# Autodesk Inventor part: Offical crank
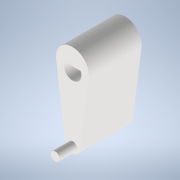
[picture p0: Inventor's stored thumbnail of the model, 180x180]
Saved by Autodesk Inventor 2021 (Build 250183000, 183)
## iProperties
Created: 2021-01
Part Number: Offical crank
Material: Generic
Document SubType Name: Modeling
Designer: Owner
Density: 1 g/cm^3
Appearance: Default
Author: Owner
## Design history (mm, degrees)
sketch "Sketch1"
  geometry: L1 (-4.752, 14.66)-(-2.155, -4.465); L2 (4.537, 14.628)-(2.038, -4.487); A1 r 4.682 centre (-0.106, 15.234) between (4.537, 14.628) and (-4.752, 14.66); A2 r 2.117 centre (-0.057, -4.18) between (-2.155, -4.465) and (2.038, -4.487); 1 further point
  constraints: 4 end point, 4 point on circle, 2 centre point, 2 tangent
extrude "Extrusion1" new body sketch "Sketch1" distance "d0" = 15; taper "d1" = 0 deg
sketch "Sketch2"
  geometry: 2 further points
hole "Hole1" sketch "Sketch2" at (-0.064, 14.158) diameter "d2" = 5; stored, may be unused: countersink angle "d6" = 90 deg, drill point angle "d8" = 118 deg; dims "d3" = 6, "d4" = 4, "d5" = 2, "d7" = 8
sketch "Sketch3"
  geometry: C1 r 1.25 at (0, -4.506); 1 further point
  constraints: 1 centre point
  dimensions: "d9" = 2.5 diameter of C1
extrude "Extrusion2" join sketch "Sketch3" distance "d10" = 5; taper "d11" = 0 deg
sketch "Sketch4"
  geometry: L1 (-2.355, 15.158)-(2.228, 15.158); A1 r 2.5 centre (-0.064, 14.158) between (-2.355, 15.158) and (2.228, 15.158) reference; 1 further point
  constraints: 2 end point, 2 point on circle, 1 horizontal
extrude "Extrusion3" join sketch "Sketch4" distance "d13" = 15; taper "d14" = 0 deg
body "Solid1"
